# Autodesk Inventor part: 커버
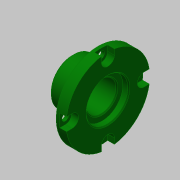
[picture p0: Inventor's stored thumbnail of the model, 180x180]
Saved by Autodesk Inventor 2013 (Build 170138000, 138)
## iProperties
Created: 2019-10
Part Number: 커버
Material: 알루미늄 6061
Document SubType Name: Modeling
Designer: mduedu
Density: 1 g/cm^3
Author: mduedu
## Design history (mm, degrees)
sketch "스케치1"
  geometry: L1 (0, 0)-(-18, 0); L2 (-18, 0)-(-18, 11.5); L3 (-18, 11.5)-(-5, 11.5); L4 (-5, 11.5)-(-5, 21); L5 (-5, 21)-(0, 21); L6 (0, 21)-(0, 0)
  constraints: 12 end point, 3 parallel, 2 perpendicular, 1 horizontal
  dimensions: "d0" = 18 distance of L1.start L1.end; "d1" = 42 diameter of L5 L1; "d2" = 23 diameter of L3 L1; "d3" = 13 distance of L2.end L3.end
revolve "회전1" sketch "스케치1" stored, may be unused: angle "d4" = 90 deg
hole "구멍1" diameter "d7" = 15; stored, may be unused: countersink angle "d11" = 90 deg, drill point angle "d13" = 118 deg; dims "d5" = 10, "d6" = 10, "d8" = 6, "d9" = 21, "d10" = 3, "d12" = 8
chamfer "모따기1" distance "d14" = 1; stored, may be unused: second distance "d15" = 2, angle "d16" = 45 deg
sketch "스케치2" dims "d17" = 36
  geometry: 6 further points
  constraints: 2 vertical alignment, 1 coincident, 7 other
  dimensions: "d20" = 360 deg dimension on point (0, 0) point (0, 18) (derived)
sketch "스케치3"
  geometry: 4 further points
  constraints: 4 other
hole "구멍2" sketch "스케치3" at (-18, 0), (0, -18), (18, 0), (0, 18) diameter "d22" = 3.4; stored, may be unused: countersink angle "d26" = 90 deg, drill point angle "d28" = 0 deg; dims "d23" = 6, "d24" = 6.5, "d25" = 3.4, "d27" = 8
sketch "스케치4"
  geometry: L1 (-21.25, 20.747)-(-21.25, 18); L2 (-14.75, 18)-(-14.75, 20.747); A1 r 3.25 centre (-18, 18) between (-19.349, 20.957) and (-16.651, 20.957) reference; A2 r 21 centre (-18, 0) between (-19.349, 20.957) and (-38.957, 1.349) reference; A3 r 21 centre (-18, 0) between (2.957, 1.349) and (-16.651, 20.957) reference; A4 r 21 centre (-18, 0) between (-14.75, 20.747) and (-21.25, 20.747); A5 r 3.25 centre (-18, 18) between (-21.25, 18) and (-14.75, 18); 1 further point
  constraints: 8 point on circle, 4 end point, 2 centre point, 2 coincident, 2 tangent, 1 parallel, 1 vertical
extrude "돌출1" cut sketch "스케치4" stored distance "d29" = 10; taper "d30" = 0 deg
chamfer "모따기3" distance "d37" = 0.5; stored, may be unused: second distance "d38" = 2, angle "d39" = 45 deg
chamfer "모따기4" distance "d40" = 0.5; stored, may be unused: second distance "d41" = 2, angle "d42" = 45 deg
node "솔리드1"
pattern_circular "원형 패턴1" dims angle "d32" = 360 deg
